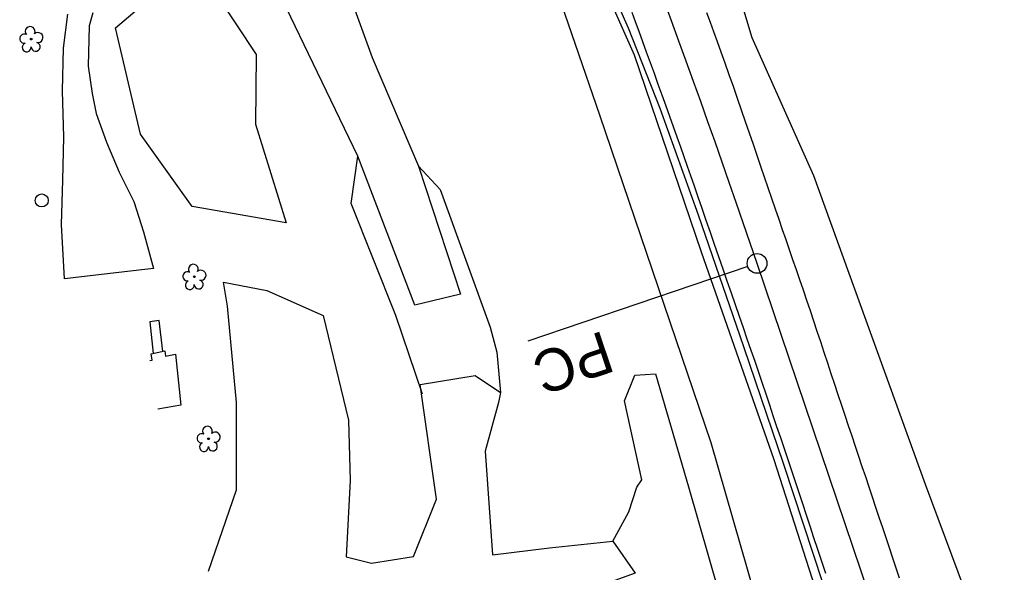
# Model space of a CAD drawing. Extents: x 478596 to 483012, y 490885 to 495165.
# Drawn here: x 480792.4 to 481167.1, y 492522.9 to 492732.2 of the extents above; entities that cross this region are included whole.
import ezdxf

# ---------------------------------------------------------------- set-up
doc = ezdxf.new("R2010")
doc.units = 0
for name, color, linetype in [('Exist Guardrail', 7, 'Continuous'), ('Exist Horizontal Alignment', 7, 'Continuous'), ('Exist Other Culture Area Outline', 7, 'Continuous'), ('Exist Roads EOP', 7, 'Continuous'), ('Exist Roads Soil', 7, 'Continuous'), ('Exist Utilities Other Pole CELL', 7, 'Continuous'), ('Exist Vegetation Hedge Row', 7, 'Continuous'), ('Exist Vegetation Tree CELL', 7, 'Continuous'), ('Exist Vegetation Woods Line', 7, 'Continuous')]:
    doc.layers.add(name, color=color, linetype=linetype)

msp = doc.modelspace()

# ---------------------------------------------------------------- linework, layer by layer
at = {"layer": 'Exist Guardrail'}
msp.add_lwpolyline([(481159.92, 492332.85), (481147.67, 492369.02), (481136.31, 492402.63), (481122.19, 492443.94), (481109.37, 492481.77), (481096.99, 492518.51), (481082.03, 492563.66), (481066.9, 492608.24), (481049.63, 492658.22), (481035.22, 492698.61), (481023.2, 492728.97), (481010.06, 492758.78), (480999.42, 492781.5)], dxfattribs=at)
at = {"layer": 'Exist Horizontal Alignment'}
for p, q in [((481314.86, 491922.25), (481071.89, 492639.91)), ((481068.34, 492638.7), (480984.96, 492610.47))]:
    msp.add_line(p, q, dxfattribs=at)
msp.add_circle((481071.89, 492639.91), 3.75, dxfattribs=at)
msp.add_arc((477373.51, 491387.79), 3904.58, 18.70399, 22.51531, dxfattribs=at)
at = {"layer": 'Exist Other Culture Area Outline'}
for points in [[(480846.7, 492606.59), (480845.22, 492618.27), (480841.72, 492617.77), (480842.96, 492605.81)], [(480841.78, 492603.17), (480842.68, 492603.31), (480842.24, 492605.67), (480847.41, 492606.73), (480847.72, 492604.82), (480851.42, 492605.57), (480853.51, 492586.2), (480844.75, 492584.74)]]:
    msp.add_lwpolyline(points, dxfattribs=at)
at = {"layer": 'Exist Roads EOP'}
for points in [[(481097.98, 492522.36), (481096.44, 492527), (481094.93, 492531.54), (481093.46, 492535.98), (481092.03, 492540.31), (481090.62, 492544.57), (481089.22, 492548.8), (481087.82, 492553), (481086.43, 492557.17), (481085.04, 492561.32), (481083.65, 492565.49), (481082.25, 492569.65), (481080.84, 492573.83), (481079.44, 492578), (481078.05, 492582.13), (481076.67, 492586.24), (481075.3, 492590.32), (481073.93, 492594.41), (481072.53, 492598.54), (481071.11, 492602.72), (481069.67, 492606.94), (481068.2, 492611.2), (481066.72, 492615.51), (481065.23, 492619.85), (481063.71, 492624.24), (481062.18, 492628.69), (481060.61, 492633.2), (481059.03, 492637.78), (481057.41, 492642.43), (481055.8, 492647.08), (481054.21, 492651.68), (481052.64, 492656.22), (481051.09, 492660.71), (481049.6, 492665.05), (481048.18, 492669.16), (481046.83, 492673.04), (481045.56, 492676.68), (481044.3, 492680.26), (481043, 492683.94), (481041.65, 492687.71), (481040.26, 492691.59), (481038.83, 492695.54), (481037.39, 492699.54), (481035.92, 492703.6), (481034.44, 492707.71), (481032.96, 492711.83), (481031.49, 492715.89), (481030.04, 492719.91), (481028.6, 492723.88), (481027.19, 492727.74), (481025.82, 492731.43), (481024.49, 492734.94)], [(481052.75, 492734.99), (481054.08, 492731.34), (481055.39, 492727.73), (481056.72, 492724.01), (481058.13, 492720.07), (481059.62, 492715.9), (481061.18, 492711.51), (481062.77, 492707.01), (481064.34, 492702.54), (481065.88, 492698.1), (481067.4, 492693.69), (481068.9, 492689.33), (481070.36, 492685.05), (481071.79, 492680.86), (481073.19, 492676.76), (481074.58, 492672.7), (481075.96, 492668.66), (481077.35, 492664.64), (481078.73, 492660.64), (481080.11, 492656.67), (481081.46, 492652.78), (481082.78, 492648.94), (481084.08, 492645.17), (481085.38, 492641.41), (481086.68, 492637.61), (481088, 492633.77), (481089.32, 492629.88), (481090.65, 492625.97), (481091.97, 492622.06), (481093.29, 492618.14), (481094.6, 492614.21), (481095.91, 492610.27), (481097.23, 492606.29), (481098.56, 492602.28), (481099.89, 492598.24), (481101.22, 492594.2), (481102.54, 492590.21), (481103.85, 492586.26), (481105.16, 492582.35), (481106.45, 492578.46), (481107.75, 492574.58), (481109.05, 492570.7), (481110.34, 492566.83), (481111.64, 492562.97), (481112.93, 492559.11), (481114.22, 492555.26), (481115.51, 492551.41), (481116.8, 492547.57), (481118.08, 492543.73), (481119.37, 492539.89), (481120.65, 492536.06), (481121.93, 492532.24), (481123.21, 492528.42), (481124.48, 492524.61), (481125.76, 492520.81)]]:
    msp.add_lwpolyline(points, dxfattribs=at)
at = {"layer": 'Exist Roads Soil'}
msp.add_lwpolyline([(480820.08, 492734.8), (480818.72, 492729.95), (480818.35, 492714.6), (480819.92, 492704.33), (480821.46, 492696.69), (480825.33, 492685.86), (480830.14, 492674.48), (480835.7, 492663.38), (480839.34, 492651.89), (480843.16, 492637.93), (480835.45, 492637.13), (480819.14, 492635.2), (480809.35, 492634.1), (480808.25, 492654.67), (480808.71, 492671.39), (480809.12, 492687.69), (480808.68, 492705.24), (480808.98, 492721.41), (480810.67, 492734.37)], dxfattribs=at)
at = {"layer": 'Exist Utilities Other Pole CELL'}
msp.add_circle((480800.77, 492663.75), 2.46, dxfattribs=at)
at = {"layer": 'Exist Vegetation Hedge Row'}
for points in [[(481071.23, 492513.93), (481054.53, 492571.95), (481012.28, 492696.13), (480993.86, 492749.69), (480974.19, 492786.51), (480967.88, 492815.61), (480971.79, 492818.74), (480977.52, 492819.35), (480978.02, 492817.58), (480978.51, 492813.62), (480990.77, 492794.88), (481002, 492771.37), (481025.27, 492718.92), (481050.65, 492644.35), (481078.23, 492565.63), (481100.49, 492496.39)], [(480945.05, 492590.36), (480935.03, 492620.16), (480918.08, 492662.57), (480920.55, 492680.49)], [(480943.52, 492676.81), (480951.79, 492667.97), (480970.72, 492615.79), (480973.32, 492606.28), (480974.69, 492591.01)], [(481017.27, 492534.67), (481023.35, 492545.77), (481026.34, 492555.13), (481028.24, 492557.95), (481021.68, 492587.87), (481025.5, 492597.54), (481033.43, 492598.02), (481045.91, 492555.24), (481064.72, 492489.67)]]:
    msp.add_lwpolyline(points, dxfattribs=at)
at = {"layer": 'Exist Vegetation Tree CELL'}
for p, q in [((480796.78, 492724.89), (480796.78, 492724.89)), ((480858.6, 492634.84), (480858.6, 492634.84)), ((480863.97, 492573.48), (480863.97, 492573.48))]:
    msp.add_line(p, q, dxfattribs=at)
for centre in [(480796.78, 492724.89), (480858.6, 492634.84), (480863.97, 492573.48)]:
    msp.add_circle(centre, 0.326, dxfattribs=at)
for centre, radius, start, end in [((480796.39, 492727.76), 1.86, 330.1651, 219.7134), ((480794.17, 492725.04), 1.73, 62.6636, 279.3457), ((480799.33, 492725.48), 1.9, 257.1011, 134.1999), ((480795.07, 492721.77), 1.69, 111.5671, 6.231), ((480798.45, 492721.99), 1.7, 181.2822, 74.56), ((480858.21, 492637.71), 1.86, 330.1651, 219.7134), ((480855.99, 492634.99), 1.73, 62.6636, 279.3457), ((480861.15, 492635.43), 1.9, 257.1011, 134.1999), ((480856.9, 492631.72), 1.69, 111.5671, 6.231), ((480860.27, 492631.94), 1.7, 181.2822, 74.56), ((480863.58, 492576.35), 1.86, 330.1651, 219.7134), ((480866.52, 492574.07), 1.9, 257.1011, 134.1999), ((480861.36, 492573.63), 1.73, 62.6636, 279.3457), ((480862.26, 492570.36), 1.69, 111.5671, 6.231), ((480865.64, 492570.58), 1.7, 181.2822, 74.56)]:
    msp.add_arc(centre, radius, start, end, dxfattribs=at)
at = {"layer": 'Exist Vegetation Woods Line'}
for points in [[(481200.38, 492382.62), (481135.69, 492556.19), (481093.4, 492673.11), (481070.04, 492725.37), (481054.31, 492777.66), (481045.71, 492826.93), (481053.22, 492857.22)], [(480942.23, 492624.03), (480920.55, 492680.49), (480876.54, 492772.09), (480902.13, 492783.76), (480925.98, 492717.91), (480943.52, 492676.81), (480959.55, 492628.24), (480942.23, 492624.03)], [(480893.46, 492655.24), (480857.8, 492661.41), (480838.21, 492688.86), (480828.68, 492729.11), (480842.69, 492741.13), (480852.25, 492754.56), (480859.73, 492752.9), (480882, 492719.02), (480881.77, 492692.66), (480893.46, 492655.24)], [(480863.95, 492523.28), (480874.59, 492554.11), (480874.64, 492587.24), (480871.17, 492623.65), (480869.6, 492632.86), (480886.04, 492629.66), (480907.39, 492620.22), (480916.99, 492580.54), (480917.69, 492557.66), (480916.17, 492528.8), (480925.72, 492526.33), (480941.71, 492528.82), (480950.45, 492550.64), (480944.15, 492593.99), (480965.04, 492597.47), (480974.69, 492591.01)], [(480974.69, 492591.01), (480973.9, 492587.17), (480968.85, 492568.82), (480971.6, 492529.52), (480993.18, 492532.19), (481017.27, 492534.67), (481025.69, 492522.53), (480985.34, 492507.97), (480980.63, 492463.84), (480989.86, 492441.63), (480998.61, 492383.63), (481010.32, 492372.34), (481020.94, 492340.18)]]:
    msp.add_lwpolyline(points, dxfattribs=at)

# ---------------------------------------------------------------- texts
at = {"layer": 'Exist Horizontal Alignment'}
msp.add_text('PC', height=16, rotation=198.704, dxfattribs=at).set_placement((481013.7, 492614.58))

doc.saveas('drawing.dxf')
